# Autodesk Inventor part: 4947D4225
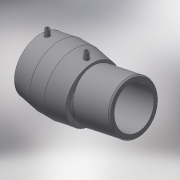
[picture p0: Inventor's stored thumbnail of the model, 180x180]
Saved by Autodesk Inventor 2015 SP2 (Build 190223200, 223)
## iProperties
Created: 2017-06
Part Number: 4947D4225
Material: Generic
Description: PLASSON ADJUSTABLE ELBOW (ONE SIDE) 225
Document SubType Name: Modeling
Designer: KIM
Mass: 55.0731 g
Surface Area: 148.067 cm^2
Volume: 55.0731 cm^3
Density: 1 g/cm^3
Appearance: Default
Author: KIM
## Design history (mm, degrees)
derived "4947D4.ipt"
feature "Solid1::4947D4.ipt"
tag "TaggingFeature1"
body "Solid1"
other parameters: "d0" = 223.65, "d2" = 282, "d3" = 105, "d4" = 52.5, "d5" = 253.8, "d7" = 225, "d8" = 168 deg, "d10" = 42, "d11" = 14, "d29" = 141, "d30" = 15, "d31" = 85.2, "d34" = 5 deg, "d41" = 4, "d42" = 14, "d43" = 0, "d48" = 202.5, "d55" = 71.19, "d57" = 168 deg, "d62" = 3, "d63" = 0, "d65" = 426, "d66" = 225, "d67" = 202.5, "d68" = 135 deg, "d69" = 124, "d70" = 104.34, "d71" = 5.64, "d_" = 225, "L_" = 426, "L_1" = 105, "D_" = 282, "A_" = 141, "d_2" = 12, "L_0" = 148, "D_1" = 225, "L_2" = 124, "d54" = 118.65, "d59" = 273.64339
